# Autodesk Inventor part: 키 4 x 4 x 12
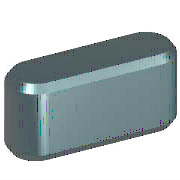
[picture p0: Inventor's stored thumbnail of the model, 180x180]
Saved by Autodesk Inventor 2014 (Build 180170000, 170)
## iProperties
IsCustomPart: 1
Created: 2012-02
Part Number: 키 4 x 4 x 12
Material: 강철, 연강
Description: 키 및 해당 키홈
Document SubType Name: Modeling
Standard: KS B 1311
Designer: mduedu
Standards Organization: KS
Language: ko-KR
Size Designation: 4 x 4 x 12
Categories: <MemberInstance><Categories><Category DisplayName="샤프트 부품" InternalName="7f7aeb1f-a693-4053-b835-cee3144e0d98" Mnemonic="SHFT"><Category DisplayName="키" Interna
Density: 1 g/cm^3
Appearance: Steel
Author: mduedu
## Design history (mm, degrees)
sketch "스케치1"
  geometry: L1 (2, 2)-(10, 2); L2 (10, -2)-(2, -2); L3 (0, 9.4)-(0, -7.4) reference; L4 (-5, 0)-(30, 0) reference; L5 (12, 0)-(12, 7); A1 r 2 centre (2, 0) between (2, 2) and (2, -2); A2 r 2 centre (10, 0) between (10, -2) and (10, 2)
  constraints: 6 end point, 5 point on circle, 4 tangent, 3 point on line, 2 centre point, 1 horizontal, 1 parallel, 1 perpendicular
  dimensions: "d0" = 2 radius of A1 (= 0.5 x PB); "d13" = 2 radius of A2 (= 0.5 x PB); "d14" = 12 distance between parallel lines of L5 L3 (= NLG)
extrude "본체1" new body sketch "스케치1" taper "d3" = 0 deg; stored distance "d4" = 10
workplane "Work Plane3"
body "Solid1"
workplane "Work Plane1"
workplane "Work Plane2"
chamfer "모따기1" distance "d8" = 0.25 (= PHH); stored, may be unused: second distance "d9" = 0.25 (= PHH), angle "d15" = 45 deg
other parameters: "d1" = -2.5 (= -PNT), "d2" = 1.5 (= PH - PNT), "NLG" = 12 [user parameter; used in 3 equation terms], "PB" = 4 [user parameter; used in 2 equation terms], "PNT" = 2.5 [user parameter; used in 2 equation terms], "PH" = 4 [user parameter; used in 1 equation term], "PHH" = 0.25 [user parameter; used in 2 equation terms], "d10" = 0, "d16" = 0, "d17" = 0, "d18" = 0, "PLB2" = 12 (= NLG) [user parameter], "WDMAX" = 12 [user parameter], "PLB1" = 12 (= NLG) [user parameter], "RR" = 0.08 [user parameter], "PUEB" = 1.8 [user parameter]
